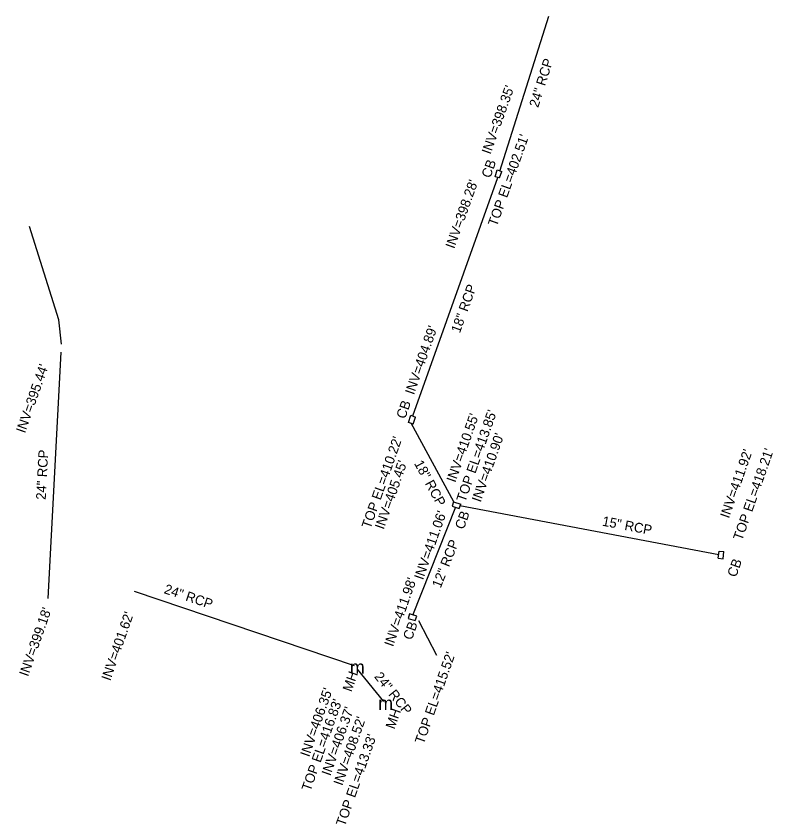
# Model space of a CAD drawing. Extents: x 1975859 to 1978323, y 778892 to 782836.
# Drawn here: x 1977254.5 to 1977565.7, y 780709.6 to 781041.7 of the extents above; entities that cross this region are included whole.
import ezdxf

# ---------------------------------------------------------------- set-up
doc = ezdxf.new("R2010")
doc.units = 0
for name, color, linetype in [('Exist Structure Minor Catch Basin', 7, 'Continuous'), ('Exist Structure Minor Catch Basin Leader', 7, 'Continuous'), ('Exist Structure Minor Catch Basin Text', 7, 'Continuous'), ('Exist Structure Minor Catch Basin Top Elevation', 7, 'Continuous'), ('Exist Structure Minor Pipes RCP 12 Inch', 7, 'Continuous'), ('Exist Structure Minor Pipes RCP 12 Inch Invert', 7, 'Continuous'), ('Exist Structure Minor Pipes RCP 12 Inch Text', 7, 'Continuous'), ('Exist Structure Minor Pipes RCP 15 Inch', 7, 'Continuous'), ('Exist Structure Minor Pipes RCP 15 Inch Invert', 7, 'Continuous'), ('Exist Structure Minor Pipes RCP 15 Inch Text', 7, 'Continuous'), ('Exist Structure Minor Pipes RCP 18 Inch', 7, 'Continuous'), ('Exist Structure Minor Pipes RCP 18 Inch Invert', 7, 'Continuous'), ('Exist Structure Minor Pipes RCP 18 Inch Text', 7, 'Continuous'), ('Exist Structure Minor Pipes RCP 24 Inch', 7, 'Continuous'), ('Exist Structure Minor Pipes RCP 24 Inch Invert', 7, 'Continuous'), ('Exist Structure Minor Pipes RCP 24 Inch Text', 7, 'Continuous'), ('Exist Structure Minor Storm Sewer Manhole CELL', 7, 'Continuous'), ('Exist Structure Minor Storm Sewer Manhole Text', 7, 'Continuous'), ('Exist Structure Minor Storm Sewer Manhole Top Elevation', 7, 'Continuous'), ('Scratch_Level_8', 7, 'Continuous')]:
    doc.layers.add(name, color=color, linetype=linetype)

msp = doc.modelspace()

# ---------------------------------------------------------------- linework, layer by layer
at = {"layer": 'Exist Structure Minor Catch Basin'}
for p, q in [((1977453.22, 780975.26), (1977454.19, 780977.84)), ((1977417.72, 780873.94), (1977418.7, 780876.83)), ((1977434.4, 780842.02), (1977437.3, 780841.06)), ((1977545.27, 780818.62), (1977545.5, 780821.57)), ((1977543.23, 780818.78), (1977545.27, 780818.62)), ((1977415.73, 780794.09), (1977418.63, 780793.19))]:
    msp.add_line(p, q, dxfattribs=at)
for points in [[(1977453.22, 780975.26), (1977451.45, 780975.66), (1977452.34, 780978.56), (1977454.19, 780977.84)], [(1977417.72, 780873.94), (1977415.89, 780874.62), (1977416.76, 780877.7), (1977418.7, 780876.83)], [(1977434.4, 780842.02), (1977433.84, 780840.19), (1977436.74, 780839.32), (1977437.3, 780841.06)], [(1977543.23, 780818.78), (1977543.58, 780821.72), (1977545.5, 780821.57)], [(1977418.63, 780793.19), (1977419.22, 780794.98), (1977416.32, 780795.89), (1977415.73, 780794.09)]]:
    msp.add_lwpolyline(points, dxfattribs=at)
at = {"layer": 'Exist Structure Minor Catch Basin Leader'}
msp.add_lwpolyline([(1977419.95, 780793.19), (1977427.42, 780778.92)], dxfattribs=at)
at = {"layer": 'Exist Structure Minor Pipes RCP 12 Inch'}
msp.add_lwpolyline([(1977417.67, 780795.46), (1977435.29, 780839.92)], dxfattribs=at)
at = {"layer": 'Exist Structure Minor Pipes RCP 15 Inch'}
msp.add_line((1977436.97, 780840.49), (1977543.42, 780820.31), dxfattribs=at)
at = {"layer": 'Exist Structure Minor Pipes RCP 18 Inch'}
for p, q in [((1977417.58, 780877.31), (1977452.56, 780975.35)), ((1977434.47, 780842.02), (1977416.91, 780874.41))]:
    msp.add_line(p, q, dxfattribs=at)
at = {"layer": 'Exist Structure Minor Pipes RCP 24 Inch'}
for p, q in [((1977453.45, 780978), (1977473.6, 781041.7)), ((1977267.72, 780802.26), (1977273.06, 780903.61)), ((1977393.68, 780774.56), (1977303.13, 780805.15)), ((1977405.68, 780759.85), (1977394.89, 780773.25))]:
    msp.add_line(p, q, dxfattribs=at)
at = {"layer": 'Scratch_Level_8'}
msp.add_lwpolyline([(1977273.14, 780906.8), (1977272.11, 780916.9), (1977259.95, 780955.17)], dxfattribs=at)

# ---------------------------------------------------------------- texts
at = {"layer": 'Exist Structure Minor Catch Basin Text'}
for rotation, p in [(70.3683, (1977449.48, 780974.86)), (70.3683, (1977414.43, 780875.84)), (70.3683, (1977438.56, 780830.38)), (70.3683, (1977550.55, 780810.75)), (70.6265, (1977417.21, 780784.92))]:
    msp.add_text('CB', height=4, rotation=rotation, dxfattribs=at).set_placement(p)
at = {"layer": 'Exist Structure Minor Catch Basin Top Elevation'}
for s, rotation, p in [("TOP EL=402.51'", 70.3683, (1977452.16, 780954.97)), ("TOP EL=413.85'", 70.6265, (1977439.17, 780841.62)), ("TOP EL=410.22'", 70.6265, (1977400.2, 780830.68)), ("TOP EL=418.21'", 70.6265, (1977552.99, 780825.8)), ("TOP EL=415.52'", 70.6265, (1977422.08, 780742.11))]:
    msp.add_text(s, height=4, rotation=rotation, dxfattribs=at).set_placement(p)
at = {"layer": 'Exist Structure Minor Pipes RCP 12 Inch Invert'}
for s, p in [("INV=411.06'", (1977421.8, 780809.66)), ("INV=411.98'", (1977409.48, 780782.19))]:
    msp.add_text(s, height=4, rotation=70.6265, dxfattribs=at).set_placement(p)
at = {"layer": 'Exist Structure Minor Pipes RCP 12 Inch Text'}
msp.add_text('12" RCP', height=4, rotation=68.374, dxfattribs=at).set_placement((1977429.06, 780806.29))
at = {"layer": 'Exist Structure Minor Pipes RCP 15 Inch Invert'}
for s, p in [("INV=410.90'", (1977445.49, 780841.59)), ("INV=411.92'", (1977547.61, 780834.97))]:
    msp.add_text(s, height=4, rotation=70.6265, dxfattribs=at).set_placement(p)
at = {"layer": 'Exist Structure Minor Pipes RCP 15 Inch Text'}
msp.add_text('15" RCP', height=4, rotation=349.2648, dxfattribs=at).set_placement((1977495.29, 780832.23))
at = {"layer": 'Exist Structure Minor Pipes RCP 18 Inch Invert'}
for s, rotation, p in [("INV=398.28'", 70.3683, (1977434.67, 780945.83)), ("INV=404.89'", 70.6265, (1977418.06, 780885.77)), ("INV=410.55'", 70.6265, (1977435.11, 780849.7)), ("INV=405.45'", 70.6265, (1977405.65, 780830.39))]:
    msp.add_text(s, height=4, rotation=rotation, dxfattribs=at).set_placement(p)
at = {"layer": 'Exist Structure Minor Pipes RCP 18 Inch Text'}
for rotation, p in [(70.3683, (1977436.97, 780911.12)), (298.4682, (1977418.05, 780857.82))]:
    msp.add_text('18" RCP', height=4, rotation=rotation, dxfattribs=at).set_placement(p)
at = {"layer": 'Exist Structure Minor Pipes RCP 24 Inch Invert'}
for s, rotation, p in [("INV=398.35'", 70.3683, (1977449.57, 780984.62)), ("INV=395.44'", 70.6265, (1977258.11, 780869.98)), ("INV=399.18'", 70.6265, (1977259.38, 780769.93)), ("INV=401.62'", 70.6265, (1977293.18, 780768.15)), ("INV=406.35'", 70.6265, (1977374.98, 780736.86)), ("INV=406.37'", 70.6265, (1977383.73, 780729.08)), ("INV=408.52'", 70.6265, (1977388.61, 780725.06))]:
    msp.add_text(s, height=4, rotation=rotation, dxfattribs=at).set_placement(p)
at = {"layer": 'Exist Structure Minor Pipes RCP 24 Inch Text'}
for rotation, p in [(72.448, (1977469.18, 781003.86)), (86.9828, (1977266.65, 780842.74)), (341.3314, (1977315.03, 780804.51)), (308.8328, (1977401.55, 780770.07))]:
    msp.add_text('24" RCP', height=4, rotation=rotation, dxfattribs=at).set_placement(p)
at = {"layer": 'Exist Structure Minor Storm Sewer Manhole CELL'}
for p in [(1977391.73, 780771.3), (1977403.38, 780756.45)]:
    msp.add_text('m', height=5.5, dxfattribs=at).set_placement(p)
at = {"layer": 'Exist Structure Minor Storm Sewer Manhole Text'}
for p in [(1977392.39, 780763.63), (1977410.06, 780748.28)]:
    msp.add_text('MH', height=4, rotation=70.6265, dxfattribs=at).set_placement(p)
at = {"layer": 'Exist Structure Minor Storm Sewer Manhole Top Elevation'}
for s, p in [("TOP EL=416.83'", (1977375.52, 780722.74)), ("TOP EL=413.33'", (1977389.67, 780708.31))]:
    msp.add_text(s, height=4, rotation=70.6265, dxfattribs=at).set_placement(p)

doc.saveas('drawing.dxf')
